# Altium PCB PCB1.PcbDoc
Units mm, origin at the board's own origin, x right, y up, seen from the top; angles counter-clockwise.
Board outline 127 x 101.6 mm, 2 copper layers (Top Layer, Bottom Layer); 3 components, 13 nets, 36 pads, 4 vias.
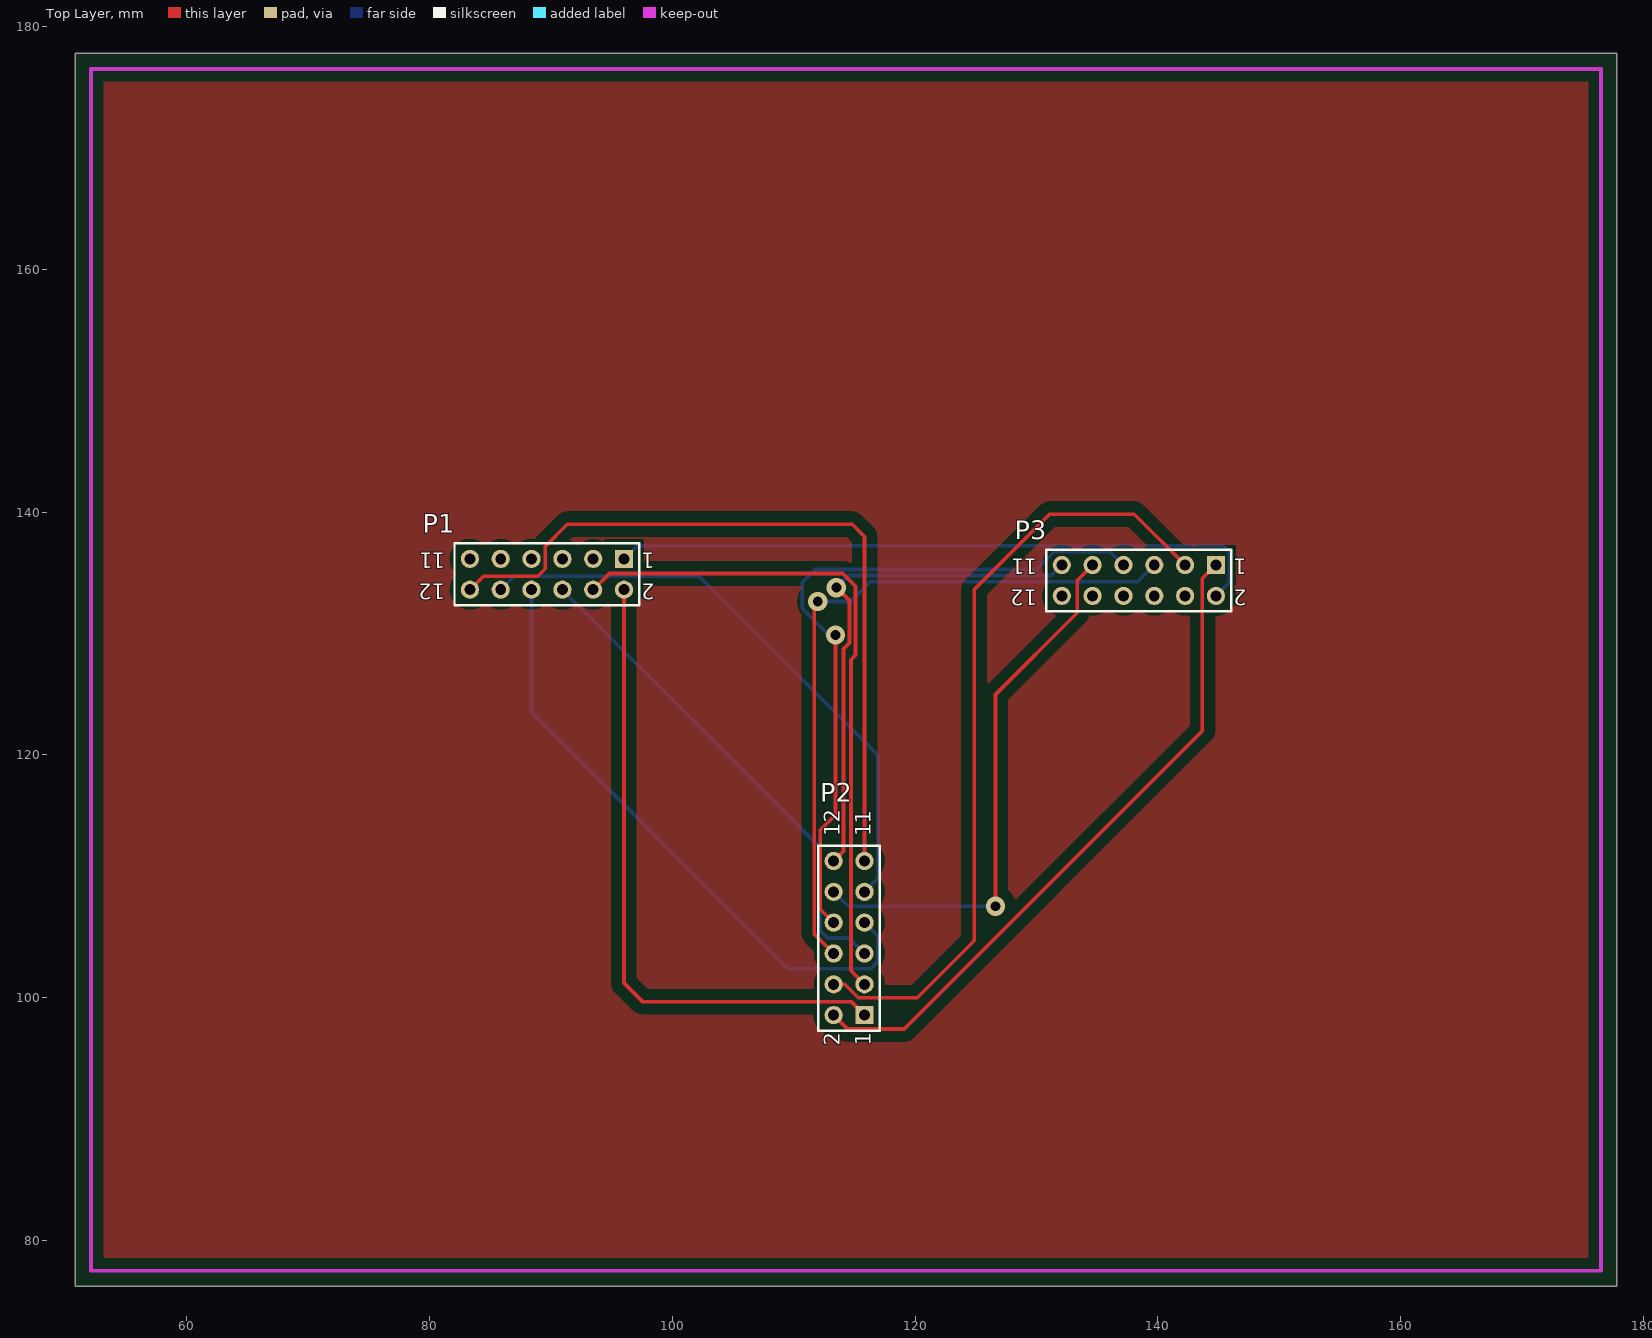
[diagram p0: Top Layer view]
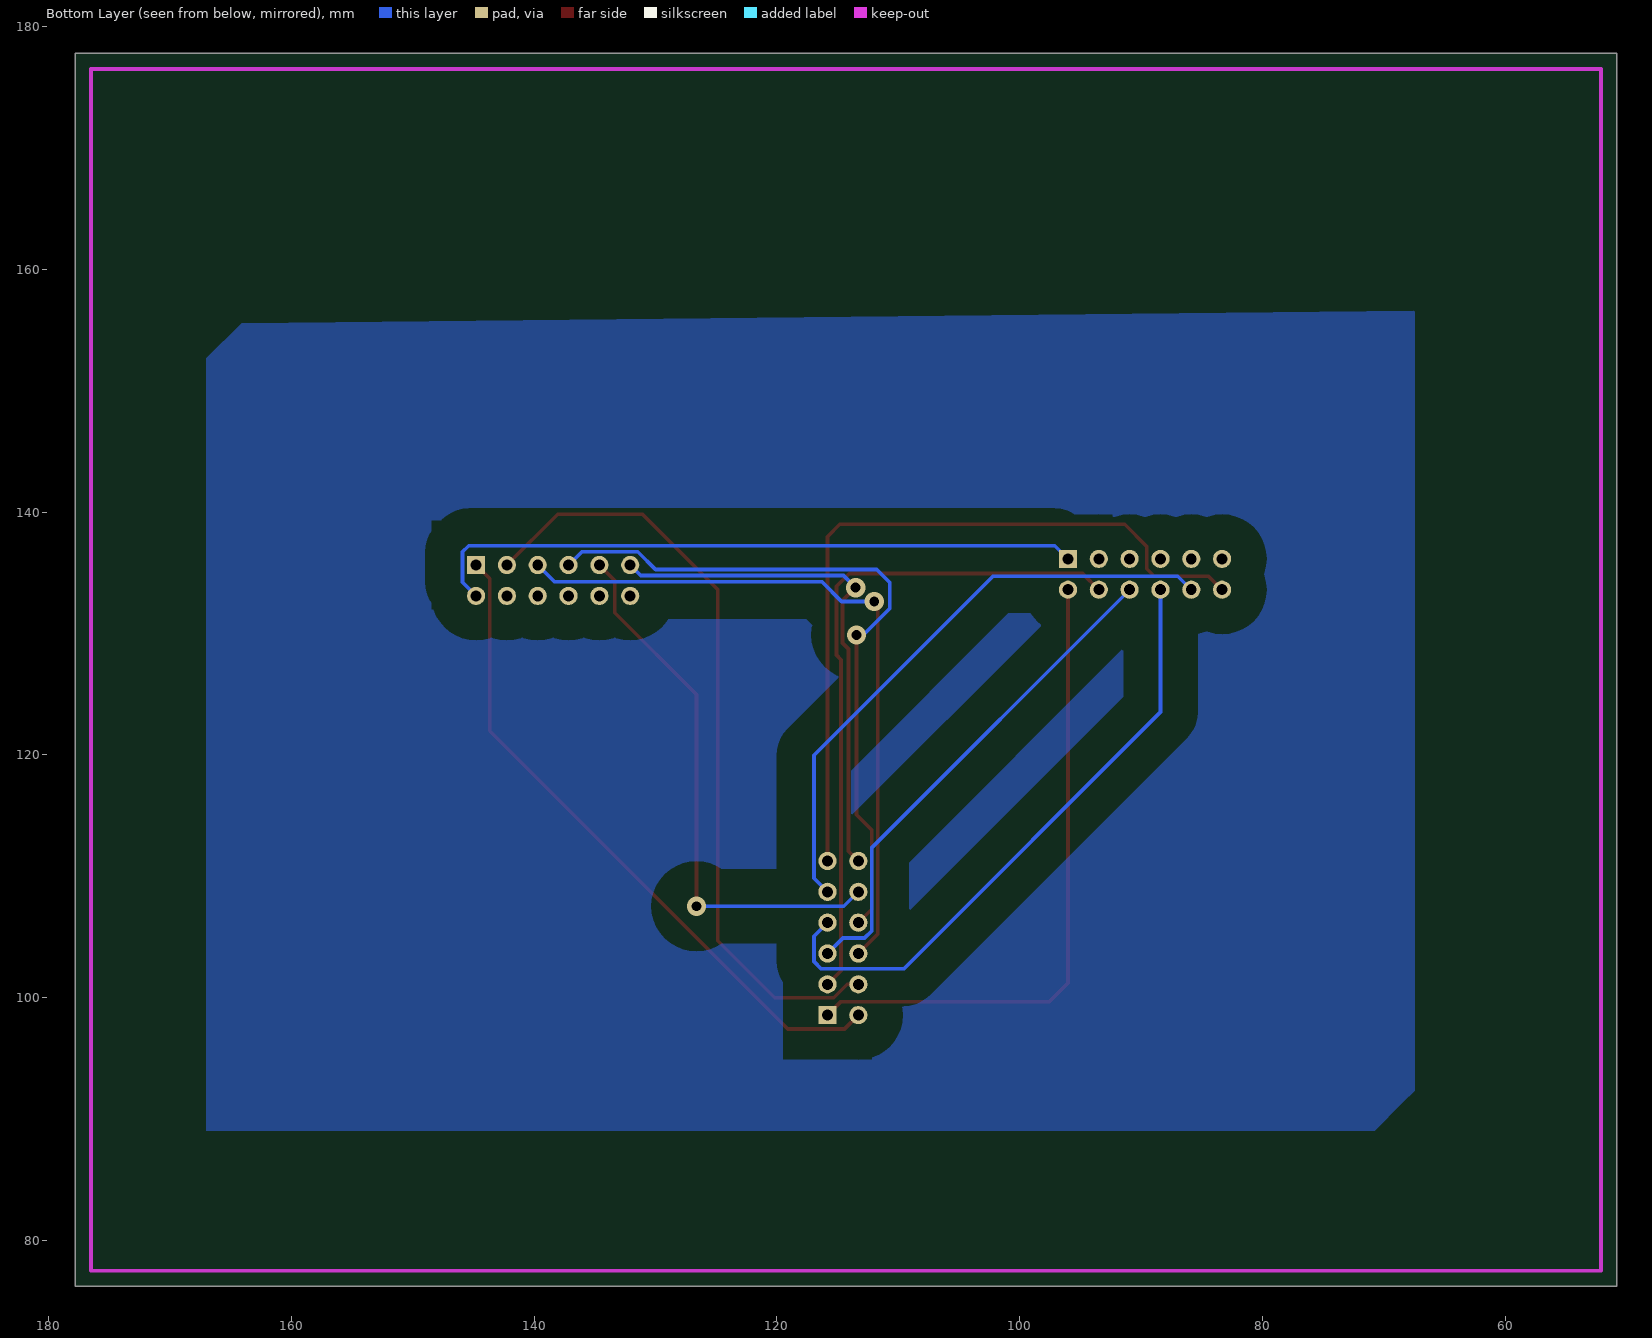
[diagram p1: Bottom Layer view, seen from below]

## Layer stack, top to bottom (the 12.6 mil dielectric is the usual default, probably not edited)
Top Layer: signal copper 0.0356
Dielectric: dielectric 0.32, FR-4, Dk 4.8
Bottom Layer: signal copper 0.0356

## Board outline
50.8,76.2 177.8,76.2 177.8,177.8 50.8,177.8

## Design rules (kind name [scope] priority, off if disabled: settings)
Clearance [All] p1: gap=2.9
PolygonConnect [All] p1: connectstyle=Relief reliefconductorwidth=0.254 reliefentries=4 polygonreliefangle="90 Angle"
RoutingVias [All] p1: holewidth=0.8 width=1.6 viastyle="Through Hole" minholewidth=0.711 minwidth=1.27 maxholewidth=0.711 maxwidth=1.27
SilkscreenOverComponentPads [All] p1: minsilkscreentomaskgap=0.254
SolderMaskExpansion [All] p1: expansion=0.102
TestPointUsage [All] p1: valid=0 allowmultiple=FALSE
Testpoint [All] p1: side=15 testpointundercomponent=TRUE minsize=1.016 maxsize=2.54 preferedsize=1.524 minholesize=0 maxholesize=1.016 preferedholesize=0.813 testpointgrid=0.025 style=1023 order=0123456789
Width [All] p1: maxlimit=0.3 minlimit=0.3 preferedwidth=0.3
23 further rules are at their usual default settings.

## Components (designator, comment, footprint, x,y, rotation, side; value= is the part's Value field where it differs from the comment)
P1 "Header 6X2" HDR2X6 96.012,136.144 r180 top
P2 "Header 6X2" HDR2X6 115.824,98.552 r90 top
P3 "Header 6X2" HDR2X6 144.78,135.636 r180 top

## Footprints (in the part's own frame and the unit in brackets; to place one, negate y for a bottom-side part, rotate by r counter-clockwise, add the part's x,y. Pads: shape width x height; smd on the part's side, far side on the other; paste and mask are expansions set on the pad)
HDR2X6 [mm] "Connector; Header; 6x2 Position"
  rect 1.5x1.5 hole 0.9: 1(0,0)
  round 1.5 hole 0.9: 2(0,2.54) 3(2.54,0) 4(2.54,2.54) 5(5.08,0) 6(5.08,2.54) 7(7.62,0) 8(7.62,2.54) 9(10.16,0) 10(10.16,2.54) 11(12.7,0) 12(12.7,2.54)
  silkscreen extent -1.27,-1.27 13.97,3.81

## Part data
P1 P2 P3: "Header, 6-Pin, Dual row"

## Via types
v1: diameter 1.6, hole 0.8, Top Layer to Bottom Layer, 4 vias

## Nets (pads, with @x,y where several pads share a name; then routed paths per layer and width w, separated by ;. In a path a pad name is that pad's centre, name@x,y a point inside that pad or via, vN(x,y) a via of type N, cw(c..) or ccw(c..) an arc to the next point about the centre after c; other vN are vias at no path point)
NetP1_1: P1.1 P3.2 | length 54.6
  Bottom Layer w0.3: P1.1 97.104,137.236 145.39,137.236 145.898,136.728 145.898,134.214 P3.2
NetP1_2: P1.2 P2.1 | length 53.3
  Top Layer w0.3: P1.2 96.012,101.194 97.536,99.67 114.706,99.67 P2.1
NetP1_4: P1.4 P2.3 | length 56
  Top Layer w0.3: P1.4 94.81,134.942 114.043,134.942 115.086,133.899 115.086,128.22 114.706,127.84 114.706,102.21 P2.3
NetP1_6: P1.6 P2.5 | length 41.3
  Bottom Layer w0.3: P1.6 112.166,112.37 112.166,105.512 112.776,104.902 114.554,104.902 P2.5
NetP1_8: P1.8 P2.7 | length 51.3
  Bottom Layer w0.3: P1.8 88.392,123.52 109.55,102.362 116.332,102.362 116.942,102.972 116.942,105.054 P2.7
NetP1_10: P1.10 P2.9 | length 49.4
  Bottom Layer w0.3: P1.10 86.97,134.722 102.184,134.722 116.942,119.964 116.942,109.83 P2.9
NetP1_12: P1.12 P2.11 | length 63
  Top Layer w0.3: P1.12 84.43,134.722 88.9,134.722 89.51,135.331 89.51,137.16 91.338,138.989 114.808,138.989 115.824,137.973 P2.11
NetP2_2: P2.2 P3.1 | length 55.2
  Top Layer w0.3: P2.2 114.427,97.409 119.101,97.409 143.662,121.971 143.662,134.518 P3.1
NetP2_4: P2.4 P3.3 | length 64.6
  Top Layer w0.3: P2.4 114.198,101.092 115.316,99.974 120.167,99.974 124.866,104.673 124.866,133.629 131.064,139.827 138.049,139.827 P3.3
NetP2_6: P2.6 P3.5 | length 58.8
  Top Layer w0.3: v1(111.963,132.632) 111.684,132.353 111.684,105.232 P2.6
  Bottom Layer w0.3: v1(111.963,132.632) 114.663,132.632 116.303,134.272 138.336,134.272 P3.5
NetP2_8: P2.8 P3.7 | length 58.4
  Top Layer w0.3: P2.8 112.184,107.272 112.184,113.81 113.436,115.062 v1(113.436,129.87)
  Bottom Layer w0.3: v1(113.436,129.87) 112.879,129.87 110.693,132.056 110.693,134.206 111.76,135.272 129.989,135.272 131.453,136.736 136.06,136.736 P3.7
NetP2_10: P2.10 P3.9 | length 45.3
  Top Layer w0.3: v1(126.619,107.518) 126.619,124.968 133.35,131.699 133.35,134.366 P3.9
  Bottom Layer w0.3: P2.10 114.478,107.518 v1(126.619,107.518)
NetP2_12: P2.12 P3.11 | length 42.8
  Top Layer w0.3: P2.12 114.097,112.065 114.097,128.727 114.586,129.217 114.586,132.708 v1(113.513,133.782)
  Bottom Layer w0.3: v1(113.513,133.782) 114.503,134.772 131.216,134.772 P3.11
pads on no net: P1.3 P1.5 P1.7 P1.9 P1.11 P3.4 P3.6 P3.8 P3.10 P3.12

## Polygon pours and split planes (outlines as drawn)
no net on Top Layer "Top Layer-No Net" (solid): 52.1,176.149 52.227,176.276 176.5,176.276 176.5,77.851 176.149,77.5 175.925,77.724 52.1,77.724
no net on Bottom Layer "Top Layer-No Net" (solid): 67.437,156.591 67.437,92.329 68.453,91.313 70.739,89.027 167.005,89.027 167.005,152.654 164.084,155.575

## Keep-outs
Keep-Out Layer:
  lines w0.3: 52.1,77.5 52.1,176.5 176.5,176.5 176.5,77.5 52.1,77.5

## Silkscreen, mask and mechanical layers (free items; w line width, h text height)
Drill Drawing:
  text ".LEGEND" at 182.88,81.28 h1.52
  text "Drill Drawing." at 182.88,78.74 h1.52

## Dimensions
52.1,77.5 to 52.1,176.5 on Mechanical 1
52.1,77.5 to 176.5,77.5 on Mechanical 1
